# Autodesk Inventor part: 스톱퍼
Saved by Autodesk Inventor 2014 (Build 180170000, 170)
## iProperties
Created: 2024-11
Part Number: 스톱퍼
Material: 일반
Document SubType Name: Modeling
Designer: dg
Density: 1 g/cm^3
Appearance: 기본값
Author: dg
Author: jhkim
Creation Date: 2024-10-25
Sending System: Autodesk Inventor 2025
Preprocessor: ST-DEVELOPER v20
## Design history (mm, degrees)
node "스톱퍼1"
node "솔리드1"
node "기준1"
